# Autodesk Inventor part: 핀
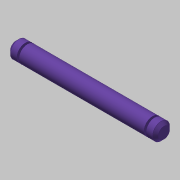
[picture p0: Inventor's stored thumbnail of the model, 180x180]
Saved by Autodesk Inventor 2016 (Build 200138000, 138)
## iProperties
Created: 2019-02
Part Number: 핀
Material: 스테인리스강
Document SubType Name: Modeling
Designer: mduedu
Density: 1 g/cm^3
Appearance: 보라색
Author: mduedu
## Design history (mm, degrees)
sketch "스케치1"
  geometry: L1 (-26, 0)-(26, 0); L2 (26, 0)-(26, 3); L3 (26, 3)-(-26, 3); L4 (-26, 3)-(-26, 0); L5 (-22.7, 3)-(-22, 3); L6 (-22, 3)-(-22, 2); L7 (-22, 2)-(-22.7, 2); L8 (-22.7, 2)-(-22.7, 3); L9 (0, 0)-(0, 3); L10 (22.7, 3)-(22, 3); L11 (22, 3)-(22, 2); L12 (22, 2)-(22.7, 2); L13 (22.7, 2)-(22.7, 3); 1 further point
  constraints: 26 end point, 4 parallel, 4 symmetric about line, 2 horizontal, 2 midpoint, 2 perpendicular, 1 coincident, 1 point on line
  dimensions: "d0" = 52 distance between parallel lines of L2 L4; "d2" = 6 diameter of L3 L1; "d3" = 4 diameter of L7 L1; "d4" = 44 distance between parallel lines of L11 L6; "d5" = 0.7 distance between parallel lines of L6 L8
revolve "회전1" sketch "스케치1" stored, may be unused: angle "d6" = 90 deg
chamfer "모따기1" distance "d7" = 1; stored, may be unused: second distance "d8" = 2, angle "d9" = 45 deg
node "솔리드1"
